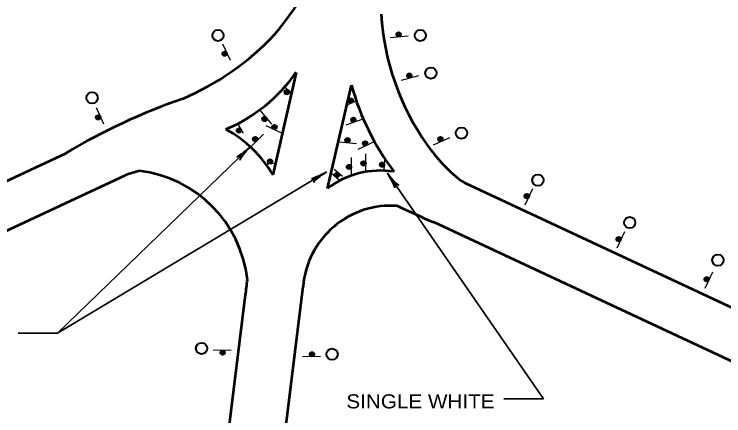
# Model space of a CAD drawing. Extents: x 393 to 1249, y -102 to 530.
# Drawn here: x 840.2 to 962.8, y 381.2 to 450.6 of the extents above; entities that cross this region are included whole.
import ezdxf
from ezdxf.enums import TextEntityAlignment as Align

# ---------------------------------------------------------------- set-up
doc = ezdxf.new("R2010")
doc.units = 0
doc.header["$LTSCALE"] = 0.97
doc.layers.add('1', color=7, linetype='Continuous', lineweight=40)
doc.layers.add('4', color=7, linetype='Continuous', lineweight=25)

msp = doc.modelspace()

# ---------------------------------------------------------------- linework, layer by layer
at = {"layer": '1', "lineweight": 53}
for p, q in [((884.8875, 422.8101), (888.97, 440.4933)), ((894.3206, 420.4602), (898.4419, 438.3114)), ((674.5966, 345.1922), (849.021, 426.5276)), ((677.8828, 338.1447), (859.4161, 422.795)), ((1080.9208, 345.4442), (918.2161, 421.3147)), ((1076.6773, 338.1447), (912.6644, 414.6252)), ((882.4301, 341.0291), (890.104, 403.5283)), ((872.7621, 342.0454), (880.1317, 402.0688))]:
    msp.add_line(p, q, dxfattribs=at)
at = {"layer": '1', "lineweight": 35}
for p, q in [((847.6419, 395.4762), (880.8897, 427.5989)), ((847.6419, 395.4762), (894.1049, 423.3294)), ((931.6085, 384.0908), (904.6769, 423.1261)), ((840.8379, 395.4762), (847.6419, 395.4762)), ((924.8045, 384.0908), (931.6085, 384.0908))]:
    msp.add_line(p, q, dxfattribs=at)
at = {"layer": '1'}
for centre, radius in [((875.3758, 446.9163), 0.972), ((910.3447, 446.9163), 0.972), ((906.5895, 447.0928), 0.3791), ((906.5807, 447.0822), 0.35), ((906.5798, 447.0919), 0.3305), ((906.6072, 447.1138), 0.3402), ((906.5895, 447.0928), 0.3013), ((906.5895, 447.0928), 0.2819), ((906.5798, 447.0919), 0.2722), ((906.5798, 447.0919), 0.2527), ((906.579, 447.1016), 0.2335), ((906.5781, 447.1113), 0.2138), ((906.5781, 447.1113), 0.1944), ((906.5554, 447.1483), 0.1555), ((906.5764, 447.1306), 0.175), ((906.5604, 447.0902), 0.1555), ((906.5642, 447.1588), 0.1461), ((906.5537, 447.1677), 0.1166), ((906.5528, 447.1774), 0.0977), ((906.5701, 447.0911), 0.1069), ((906.552, 447.187), 0.0778), ((906.5503, 447.2064), 0.0583), ((906.5486, 447.2258), 0.0389), ((906.5469, 447.2451), 0.0194), ((906.7217, 447.1433), 0.00972), ((876.5287, 443.7638), 0.3791), ((876.5028, 443.7732), 0.3402), ((876.5416, 443.7591), 0.35), ((876.5328, 443.755), 0.3305), ((876.5287, 443.7638), 0.3013), ((876.5287, 443.7638), 0.2819), ((876.5328, 443.755), 0.2722), ((876.5328, 443.755), 0.2527), ((876.524, 443.7509), 0.2335), ((876.5152, 443.7467), 0.2138), ((876.5152, 443.7467), 0.1944), ((876.4975, 443.7385), 0.175), ((876.4752, 443.7174), 0.1461), ((876.4881, 443.7127), 0.1555), ((876.4705, 443.7045), 0.1166), ((876.4617, 443.7004), 0.0977), ((876.4529, 443.6963), 0.0778), ((876.4353, 443.6881), 0.0583), ((876.4177, 443.6798), 0.0389), ((876.4, 443.6716), 0.0194), ((876.541, 443.7373), 0.1555), ((876.4359, 443.8707), 0.00972), ((876.5369, 443.7462), 0.1069), ((908.4289, 439.9822), 0.3791), ((908.422, 439.9702), 0.35), ((908.4195, 439.9796), 0.3305), ((908.4426, 440.006), 0.3402), ((912.1745, 440.4105), 0.972), ((908.4289, 439.9822), 0.3013), ((908.4289, 439.9822), 0.2819), ((908.4195, 439.9796), 0.2722), ((908.4195, 439.9796), 0.2527), ((908.417, 439.989), 0.2335), ((908.4145, 439.9984), 0.2138), ((908.4145, 439.9984), 0.1944), ((908.3856, 440.0309), 0.1555), ((908.4094, 440.0172), 0.175), ((908.4007, 439.9746), 0.1555), ((908.3925, 440.0428), 0.1461), ((908.3806, 440.0497), 0.1166), ((908.3781, 440.0591), 0.0977), ((908.3756, 440.0685), 0.0778), ((908.4101, 439.9771), 0.1069), ((908.3705, 440.0873), 0.0583), ((908.3655, 440.106), 0.0389), ((908.3605, 440.1248), 0.0194), ((908.5503, 440.0549), 0.00972), ((853.6218, 436.141), 0.972), ((887.2679, 437.1153), 0.3791), ((887.2601, 437.1313), 0.3402), ((887.3012, 437.1349), 0.35), ((887.2949, 437.1275), 0.3305), ((887.2875, 437.1337), 0.3013), ((887.2875, 437.1337), 0.2819), ((887.2949, 437.1275), 0.2722), ((887.2949, 437.1275), 0.2527), ((887.2887, 437.12), 0.2335), ((887.2825, 437.1126), 0.2138), ((887.2825, 437.1126), 0.1944), ((887.27, 437.0977), 0.175), ((887.2587, 437.0691), 0.1461), ((887.2724, 437.0703), 0.1555), ((887.2599, 437.0554), 0.1166), ((887.3098, 437.115), 0.1555), ((887.2536, 437.048), 0.0977), ((887.2474, 437.0405), 0.0778), ((887.2349, 437.0256), 0.0583), ((887.2329, 437.0333), 0.0389), ((887.3024, 437.1212), 0.1069), ((887.2294, 437.0142), 0.0194), ((887.2498, 437.0223), 0.00972), ((898.3356, 435.6502), 0.3791), ((898.3393, 435.6117), 0.35), ((898.3352, 435.6205), 0.3305), ((898.3534, 435.6505), 0.3402), ((898.344, 435.6247), 0.3013), ((898.344, 435.6247), 0.2819), ((898.3352, 435.6205), 0.2722), ((898.3352, 435.6205), 0.2527), ((898.3311, 435.6294), 0.2335), ((898.327, 435.6382), 0.2138), ((898.327, 435.6382), 0.1944), ((898.2929, 435.6652), 0.1555), ((898.3187, 435.6558), 0.175), ((898.2976, 435.6781), 0.1461), ((898.3176, 435.6123), 0.1555), ((898.2847, 435.6828), 0.1166), ((898.2806, 435.6916), 0.0977), ((898.2765, 435.7004), 0.0778), ((898.2683, 435.718), 0.0583), ((898.3264, 435.6164), 0.1069), ((898.276, 435.7166), 0.0389), ((898.2602, 435.7278), 0.0194), ((898.2589, 435.706), 0.00972), ((854.6686, 432.7594), 0.3791), ((854.6428, 432.7688), 0.3402), ((854.6815, 432.7547), 0.35), ((854.6727, 432.7506), 0.3305), ((854.6686, 432.7594), 0.3013), ((854.6686, 432.7594), 0.2819), ((854.6727, 432.7506), 0.2722), ((854.6727, 432.7506), 0.2527), ((854.6639, 432.7465), 0.2335), ((854.6551, 432.7424), 0.2138), ((854.6551, 432.7424), 0.1944), ((854.6375, 432.7342), 0.175), ((854.6152, 432.7131), 0.1461), ((854.6281, 432.7084), 0.1555), ((854.6105, 432.7001), 0.1166), ((854.6017, 432.696), 0.0977), ((854.5929, 432.6919), 0.0778), ((854.5752, 432.6837), 0.0583), ((854.5576, 432.6755), 0.0389), ((854.54, 432.6673), 0.0194), ((854.681, 432.733), 0.1555), ((854.5759, 432.8663), 0.00972), ((854.6768, 432.7418), 0.1069), ((883.4068, 432.4789), 0.3791), ((883.3794, 432.4813), 0.3402), ((883.4205, 432.4777), 0.35), ((883.413, 432.4714), 0.3305), ((883.4068, 432.4789), 0.3013), ((883.4068, 432.4789), 0.2819), ((883.413, 432.4714), 0.2722), ((883.413, 432.4714), 0.2527), ((883.4056, 432.4652), 0.2335), ((883.3981, 432.4589), 0.2138), ((883.3981, 432.4589), 0.1944), ((883.3832, 432.4464), 0.175), ((883.3671, 432.4202), 0.1461), ((883.3808, 432.419), 0.1555), ((883.3659, 432.4065), 0.1166), ((883.3585, 432.4003), 0.0977), ((883.4255, 432.4565), 0.1555), ((883.351, 432.3941), 0.0778), ((883.3362, 432.3816), 0.0583), ((883.2895, 432.5581), 0.00972), ((883.3213, 432.3691), 0.0389), ((883.3064, 432.3566), 0.0194), ((883.4193, 432.464), 0.1069), ((898.7845, 432.3435), 0.3791), ((898.7787, 432.331), 0.35), ((898.7753, 432.3402), 0.3305), ((898.7961, 432.3684), 0.3402), ((898.7845, 432.3435), 0.3013), ((898.7845, 432.3435), 0.2819), ((898.7753, 432.3402), 0.2722), ((898.7753, 432.3402), 0.2527), ((898.772, 432.3493), 0.2335), ((898.7687, 432.3584), 0.2138), ((898.7687, 432.3584), 0.1944), ((898.7371, 432.3883), 0.1555), ((898.762, 432.3767), 0.175), ((898.7429, 432.4008), 0.1461), ((898.7571, 432.3335), 0.1555), ((898.7305, 432.4066), 0.1166), ((898.7271, 432.4157), 0.0977), ((898.7238, 432.4249), 0.0778), ((898.7172, 432.4431), 0.0583), ((898.7662, 432.3369), 0.1069), ((898.7105, 432.4614), 0.0389), ((898.7039, 432.4797), 0.0194), ((898.899, 432.4266), 0.00972), ((879.0003, 430.4948), 0.3791), ((878.9985, 430.5126), 0.3402), ((879.0383, 430.5019), 0.35), ((879.0299, 430.497), 0.3305), ((879.025, 430.5054), 0.3013), ((879.025, 430.5054), 0.2819), ((879.0299, 430.497), 0.2722), ((879.0299, 430.497), 0.2527), ((879.0215, 430.4922), 0.2335), ((879.013, 430.4873), 0.2138), ((879.013, 430.4873), 0.1944), ((878.9962, 430.4776), 0.175), ((878.9758, 430.4546), 0.1461), ((878.9891, 430.451), 0.1555), ((878.9723, 430.4413), 0.1166), ((878.9638, 430.4365), 0.0977), ((878.9554, 430.4316), 0.0778), ((879.0396, 430.4802), 0.1555), ((879.0347, 430.4886), 0.1069), ((885.1453, 431.0803), 0.3791), ((885.1324, 431.0756), 0.35), ((885.1365, 431.0844), 0.3305), ((885.1711, 431.0897), 0.3402), ((885.1453, 431.0803), 0.3013), ((885.1453, 431.0803), 0.2819), ((885.1365, 431.0844), 0.2722), ((885.1365, 431.0844), 0.2527), ((885.1406, 431.0932), 0.2335), ((885.1447, 431.102), 0.2138), ((885.1447, 431.102), 0.1944), ((885.1189, 431.0926), 0.1555), ((885.1529, 431.1196), 0.175), ((885.1435, 431.1455), 0.1555), ((885.1564, 431.1502), 0.1461), ((885.1277, 431.0885), 0.1069), ((885.1517, 431.1631), 0.1166), ((885.1558, 431.1719), 0.0977), ((885.1599, 431.1807), 0.0778), ((885.1682, 431.1983), 0.0583), ((885.1764, 431.216), 0.0389), ((885.1846, 431.2336), 0.0194), ((885.2851, 431.058), 0.00972), ((917.4604, 430.0417), 0.972), ((878.9386, 430.4219), 0.0583), ((878.9393, 430.4297), 0.0389), ((878.9295, 430.413), 0.0194), ((878.9514, 430.4136), 0.00972), ((881.7927, 429.0166), 0.3791), ((881.7927, 429.0028), 0.35), ((881.7927, 429.0441), 0.3402), ((881.7858, 429.0097), 0.3305), ((881.7927, 429.0166), 0.3013), ((881.7927, 429.0166), 0.2819), ((881.7858, 429.0097), 0.2722), ((881.7858, 429.0097), 0.2527), ((913.8263, 428.9956), 0.3791), ((913.8216, 428.9827), 0.35), ((913.8175, 428.9915), 0.3305), ((913.8357, 429.0215), 0.3402), ((913.8263, 428.9956), 0.3013), ((913.8263, 428.9956), 0.2819), ((913.8175, 428.9915), 0.2722), ((881.779, 429.0166), 0.2335), ((881.7721, 429.0234), 0.2138), ((881.7309, 429.0372), 0.1555), ((881.7721, 429.0234), 0.1944), ((881.7584, 429.0372), 0.175), ((881.7309, 429.0509), 0.1461), ((881.7171, 429.0509), 0.1166), ((881.7102, 429.0578), 0.0977), ((881.7721, 428.9959), 0.1555), ((881.7034, 429.0647), 0.0778), ((881.6896, 429.0784), 0.0583), ((881.6759, 429.0922), 0.0389), ((881.6621, 429.1059), 0.0194), ((881.779, 429.0028), 0.1069), ((881.8614, 429.1403), 0.00972), ((897.7591, 428.8098), 0.3791), ((897.7486, 428.8009), 0.35), ((897.7494, 428.8106), 0.3305), ((897.7802, 428.8274), 0.3402), ((897.7591, 428.8098), 0.3013), ((897.7591, 428.8098), 0.2819), ((897.7494, 428.8106), 0.2722), ((897.7494, 428.8106), 0.2527), ((897.7503, 428.8203), 0.2335), ((897.7511, 428.83), 0.2138), ((897.7511, 428.83), 0.1944), ((897.7301, 428.8123), 0.1555), ((897.7528, 428.8493), 0.175), ((897.7351, 428.8704), 0.1555), ((897.7457, 428.8792), 0.1461), ((897.7368, 428.8898), 0.1166), ((897.7397, 428.8115), 0.1069), ((897.7377, 428.8995), 0.0977), ((897.7385, 428.9091), 0.0778), ((897.7402, 428.9285), 0.0583), ((897.7419, 428.9479), 0.0389), ((897.7436, 428.9672), 0.0194), ((897.8981, 428.8366), 0.00972), ((900.8064, 428.2625), 0.3791), ((900.8017, 428.2496), 0.35), ((900.7976, 428.2584), 0.3305), ((900.8158, 428.2883), 0.3402), ((900.8064, 428.2625), 0.3013), ((900.8064, 428.2625), 0.2819), ((900.7976, 428.2584), 0.2722), ((900.7976, 428.2584), 0.2527), ((900.7935, 428.2672), 0.2335), ((900.7894, 428.276), 0.2138), ((900.7894, 428.276), 0.1944), ((900.7554, 428.303), 0.1555), ((900.7812, 428.2936), 0.175), ((900.7601, 428.3159), 0.1461), ((900.78, 428.2502), 0.1555), ((900.7471, 428.3206), 0.1166), ((900.743, 428.3295), 0.0977), ((900.7389, 428.3383), 0.0778), ((900.7307, 428.3559), 0.0583), ((900.7888, 428.2543), 0.1069), ((900.7225, 428.3735), 0.0389), ((900.7143, 428.3911), 0.0194), ((900.9133, 428.3552), 0.00972), ((913.8175, 428.9915), 0.2527), ((913.8134, 429.0003), 0.2335), ((913.8093, 429.0091), 0.2138), ((913.8093, 429.0091), 0.1944), ((913.7752, 429.0362), 0.1555), ((913.801, 429.0268), 0.175), ((913.7799, 429.0491), 0.1461), ((913.7999, 428.9833), 0.1555), ((913.767, 429.0538), 0.1166), ((913.7629, 429.0626), 0.0977), ((913.7588, 429.0714), 0.0778), ((913.7506, 429.089), 0.0583), ((913.8087, 428.9874), 0.1069), ((913.7424, 429.1066), 0.0389), ((913.7341, 429.1243), 0.0194), ((913.9332, 429.0884), 0.00972), ((884.3789, 425.1521), 0.3791), ((884.3692, 425.1147), 0.35), ((884.3684, 425.1244), 0.3305), ((884.3957, 425.1463), 0.3402), ((884.378, 425.1252), 0.3013), ((884.378, 425.1252), 0.2819), ((884.3684, 425.1244), 0.2722), ((884.3684, 425.1244), 0.2527), ((884.3675, 425.1341), 0.2335), ((884.3667, 425.1438), 0.2138), ((884.3667, 425.1438), 0.1944), ((884.3439, 425.1808), 0.1555), ((884.365, 425.1631), 0.175), ((884.349, 425.1227), 0.1555), ((884.3527, 425.1913), 0.1461), ((884.3422, 425.2002), 0.1166), ((884.3414, 425.2098), 0.0977), ((884.3587, 425.1235), 0.1069), ((884.3405, 425.2195), 0.0778), ((884.3388, 425.2389), 0.0583), ((884.3456, 425.2349), 0.0389), ((884.3346, 425.2508), 0.0194), ((884.3259, 425.2307), 0.00972), ((898.0182, 424.2025), 0.3791), ((897.9987, 424.222), 0.3402), ((898.0279, 424.1928), 0.35), ((898.0182, 424.1928), 0.3305), ((898.0182, 424.2025), 0.3013), ((898.0182, 424.2025), 0.2819), ((898.0182, 424.1928), 0.2722), ((898.0182, 424.1928), 0.2527), ((898.0084, 424.1928), 0.2335), ((897.9987, 424.1928), 0.2138), ((897.9987, 424.1928), 0.1944), ((897.9793, 424.1928), 0.175), ((900.524, 424.8145), 0.3791), ((900.5045, 424.8339), 0.3402), ((900.5337, 424.8048), 0.35), ((900.524, 424.8048), 0.3305), ((900.524, 424.8145), 0.3013), ((900.524, 424.8145), 0.2819), ((900.524, 424.8048), 0.2722), ((900.524, 424.8048), 0.2527), ((900.5142, 424.8048), 0.2335), ((900.5045, 424.8048), 0.2138), ((900.4559, 424.795), 0.1461), ((900.5045, 424.8048), 0.1944), ((900.4851, 424.8048), 0.175), ((900.4656, 424.7853), 0.1555), ((900.4462, 424.7853), 0.1166), ((900.4365, 424.7853), 0.0977), ((900.4268, 424.7853), 0.0778), ((900.4073, 424.7853), 0.0583), ((900.3879, 424.7853), 0.0389), ((900.3684, 424.7853), 0.0194), ((900.524, 424.7853), 0.1555), ((900.524, 424.795), 0.1069), ((900.4851, 424.9506), 0.00972), ((903.7317, 424.5864), 0.3791), ((903.7403, 424.602), 0.3402), ((903.7668, 424.5704), 0.35), ((903.7572, 424.5712), 0.3305), ((903.758, 424.5809), 0.3013), ((903.758, 424.5809), 0.2819), ((903.7572, 424.5712), 0.2722), ((903.7572, 424.5712), 0.2527), ((903.7475, 424.5721), 0.2335), ((903.7378, 424.5729), 0.2138), ((903.6974, 424.5569), 0.1555), ((903.6885, 424.5675), 0.1461), ((903.7378, 424.5729), 0.1944), ((903.7184, 424.5746), 0.175), ((903.678, 424.5586), 0.1166), ((903.6683, 424.5595), 0.0977), ((903.6586, 424.5603), 0.0778), ((903.6393, 424.562), 0.0583), ((903.7555, 424.5519), 0.1555), ((903.6444, 424.568), 0.0389), ((903.6268, 424.5599), 0.0194), ((903.6451, 424.5479), 0.00972), ((903.7563, 424.5615), 0.1069), ((895.9284, 422.8267), 0.3791), ((895.901, 422.8243), 0.3402), ((895.9421, 422.8279), 0.35), ((895.9358, 422.8204), 0.3305), ((897.9501, 424.1831), 0.1461), ((897.9598, 424.1734), 0.1555), ((897.9404, 424.1734), 0.1166), ((897.9307, 424.1734), 0.0977), ((897.921, 424.1734), 0.0778), ((897.9015, 424.1734), 0.0583), ((897.8821, 424.1734), 0.0389), ((897.8626, 424.1734), 0.0194), ((898.0182, 424.1734), 0.1555), ((898.0182, 424.1831), 0.1069), ((897.9793, 424.3386), 0.00972), ((895.9284, 422.8267), 0.3013), ((895.9284, 422.8267), 0.2819), ((895.9358, 422.8204), 0.2722), ((895.9358, 422.8204), 0.2527), ((895.9296, 422.813), 0.2335), ((895.9233, 422.8056), 0.2138), ((895.9233, 422.8056), 0.1944), ((895.9108, 422.7907), 0.175), ((895.8995, 422.7621), 0.1461), ((895.9132, 422.7633), 0.1555), ((895.9007, 422.7484), 0.1166), ((895.7991, 422.8844), 0.00972), ((895.9507, 422.8079), 0.1555), ((895.8945, 422.7409), 0.0977), ((895.8882, 422.7335), 0.0778), ((895.8757, 422.7186), 0.0583), ((895.8632, 422.7037), 0.0389), ((895.9433, 422.8142), 0.1069), ((895.8698, 422.7056), 0.0194), ((930.6754, 421.9094), 0.972), ((928.7513, 419.1461), 0.3791), ((928.7419, 419.1719), 0.3402), ((928.756, 419.1331), 0.35), ((928.7472, 419.1372), 0.3305), ((928.7513, 419.1461), 0.3013), ((928.7513, 419.1461), 0.2819), ((928.7472, 419.1372), 0.2722), ((928.7472, 419.1372), 0.2527), ((928.7383, 419.1414), 0.2335), ((928.7295, 419.1455), 0.2138), ((928.6861, 419.1443), 0.1555), ((928.7295, 419.1455), 0.1944), ((928.6814, 419.1572), 0.1461), ((928.7119, 419.1537), 0.175), ((928.6685, 419.1525), 0.1166), ((928.6597, 419.1566), 0.0977), ((928.6508, 419.1607), 0.0778), ((928.6332, 419.1689), 0.0583), ((928.6156, 419.1771), 0.0389), ((928.598, 419.1853), 0.0194), ((928.7389, 419.1196), 0.1555), ((928.743, 419.1284), 0.1069), ((928.7735, 419.2858), 0.00972), ((946.5335, 414.5903), 0.972), ((944.6284, 411.7142), 0.3791), ((944.619, 411.7401), 0.3402), ((944.6331, 411.7013), 0.35), ((944.6243, 411.7054), 0.3305), ((944.6284, 411.7142), 0.3013), ((944.6284, 411.7142), 0.2819), ((944.6243, 411.7054), 0.2722), ((944.6243, 411.7054), 0.2527), ((944.6155, 411.7095), 0.2335), ((944.6067, 411.7136), 0.2138), ((944.5632, 411.7124), 0.1555), ((944.6067, 411.7136), 0.1944), ((944.5585, 411.7254), 0.1461), ((944.5891, 411.7218), 0.175), ((944.5456, 411.7207), 0.1166), ((944.5368, 411.7248), 0.0977), ((944.528, 411.7289), 0.0778), ((944.5104, 411.7371), 0.0583), ((944.4927, 411.7453), 0.0389), ((944.4751, 411.7535), 0.0194), ((944.6161, 411.6878), 0.1555), ((944.6202, 411.6966), 0.1069), ((944.6507, 411.854), 0.00972), ((961.7815, 408.0845), 0.972), ((959.8298, 404.7891), 0.3791), ((959.8204, 404.815), 0.3402), ((959.8345, 404.7762), 0.35), ((959.8257, 404.7803), 0.3305), ((959.8298, 404.7891), 0.3013), ((959.8298, 404.7891), 0.2819), ((959.8257, 404.7803), 0.2722), ((959.8257, 404.7803), 0.2527), ((959.8169, 404.7844), 0.2335), ((959.8081, 404.7885), 0.2138), ((959.7646, 404.7873), 0.1555), ((959.8081, 404.7885), 0.1944), ((959.7599, 404.8003), 0.1461), ((959.7905, 404.7967), 0.175), ((959.747, 404.7956), 0.1166), ((959.7382, 404.7997), 0.0977), ((959.7294, 404.8038), 0.0778), ((959.7118, 404.812), 0.0583), ((959.6942, 404.8202), 0.0389), ((959.6766, 404.8284), 0.0194), ((959.8175, 404.7627), 0.1555), ((959.8216, 404.7715), 0.1069), ((959.8521, 404.9289), 0.00972), ((872.5294, 392.8364), 0.972), ((876.1684, 392.1121), 0.3791), ((876.1783, 392.1216), 0.35), ((895.0966, 391.8199), 0.972), ((876.1486, 392.093), 0.3402), ((876.1781, 392.1119), 0.3305), ((876.1684, 392.1121), 0.3013), ((876.1684, 392.1121), 0.2819), ((876.1781, 392.1119), 0.2722), ((876.1781, 392.1119), 0.2527), ((876.1779, 392.1022), 0.2335), ((876.1778, 392.0925), 0.2138), ((876.1778, 392.0925), 0.1944), ((876.1774, 392.073), 0.175), ((876.0317, 392.0756), 0.00972), ((876.1866, 392.0437), 0.1461), ((876.1965, 392.0533), 0.1555), ((876.1976, 392.1116), 0.1555), ((876.1962, 392.0338), 0.1166), ((876.1878, 392.1117), 0.1069), ((876.196, 392.0241), 0.0977), ((876.1959, 392.0144), 0.0778), ((876.1955, 391.9949), 0.0583), ((876.1952, 391.9755), 0.0389), ((876.1948, 391.9561), 0.0194), ((891.6199, 391.8278), 0.3791), ((891.6001, 391.8469), 0.3402), ((891.6298, 391.8182), 0.35), ((891.6296, 391.8279), 0.3305), ((891.6199, 391.8278), 0.3013), ((891.6199, 391.8278), 0.2819), ((891.6296, 391.8279), 0.2722), ((891.6296, 391.8279), 0.2527), ((891.6294, 391.8377), 0.2335), ((891.6293, 391.8474), 0.2138), ((891.6293, 391.8474), 0.1944), ((891.6289, 391.8668), 0.175), ((891.4831, 391.8643), 0.00972), ((891.6381, 391.8961), 0.1461), ((891.648, 391.8866), 0.1555), ((891.649, 391.8283), 0.1555), ((891.6477, 391.906), 0.1166), ((891.6393, 391.8281), 0.1069), ((891.6475, 391.9157), 0.0977), ((891.6473, 391.9255), 0.0778), ((891.647, 391.9449), 0.0583), ((891.6467, 391.9643), 0.0389), ((891.6463, 391.9838), 0.0194)]:
    msp.add_circle(centre, radius, dxfattribs=at)
at = {"layer": '1', "lineweight": 53}
for centre, radius, start, end in [((838.0728, 486.6848), 61.5345, 319.99373, 340.00633), ((850.4999, 479.7458), 47.6298, 293.22493, 316.77535), ((865.562, 456.9458), 28.5302, 293.08907, 324.91903), ((903.6451, 335.8354), 105.872, 108.93946, 121.06067), ((866.5185, 412.0069), 21.3097, 30.45813, 61.29534), ((938.0157, 446.9321), 32.5487, 215.37581, 230.30556), ((877.337, 368.3284), 57.3391, 105.73397, 108.21258), ((859.2772, 402.3578), 21.3097, 6.34554, 83.3181), ((903.4999, 408.4109), 15.1552, 81.2821, 127.28757), ((904.9128, 399.4693), 25.5773, 58.65985, 61.21963), ((905.2126, 402.3401), 15.1552, 85.47195, 175.50333), ((999.7154, 616.1069), 219.4829, 244.83939, 246.63305), ((825.3366, 410.1386), 55.3862, 351.62224, 354.37838), ((859.2772, 402.3578), 21.3097, 6.32047, 6.34554)]:
    msp.add_arc(centre, radius, start, end, dxfattribs=at)
for centre, major_axis, start_param, end_param in [((942.696, 453.3676), (1.5595, -41.973), 4.74374174, 5.32357861), ((936.1557, 449.2676), (-7.3859, 41.3475), 1.66994276, 2.07069625)]:
    msp.add_ellipse(centre, major_axis=major_axis, ratio=0.934252, start_param=start_param, end_param=end_param, dxfattribs=at)
at = {"layer": '1'}
for centre, major_axis, ratio, start_param, end_param in [((879.9636, 426.99), (1.3464, 1.0635), 0.07063, 3.14071475, 5.41810995), ((880.3136, 426.6687), (1.1428, 1.3152), 0.122415, 0.89635335, 3.14159265), ((893.0649, 422.9458), (-1.5521, -0.7314), 0.07063, 6.28230741, 8.55970261), ((893.3332, 422.5537), (1.4107, 1.0226), 0.122415, 0.89635335, 3.14159265), ((905.1261, 422.1129), (-0.829, 1.5022), 0.07063, 3.14071475, 5.41810995), ((905.5002, 422.4056), (-1.1106, 1.3425), 0.122415, 0.89635335, 3.14159265)]:
    msp.add_ellipse(centre, major_axis=major_axis, ratio=ratio, start_param=start_param, end_param=end_param, dxfattribs=at)
at = {"layer": '4'}
for p, q in [((905.1436, 446.5565), (908.2423, 446.8276)), ((877.5271, 442.5885), (876.2127, 445.4074)), ((907.0981, 439.2029), (910.1026, 440.0079)), ((888.1813, 436.886), (886.8432, 438.009)), ((897.7418, 434.9191), (899.3251, 435.6575)), ((855.6671, 431.5842), (854.3526, 434.4031)), ((884.6754, 431.6022), (882.6761, 433.9847)), ((897.5267, 431.4512), (900.4496, 432.515)), ((900.6645, 431.8324), (900.6699, 431.8349)), ((879.7802, 429.9669), (878.9068, 431.4798)), ((883.625, 431.3387), (886.4439, 430.0243)), ((881.0299, 427.6763), (883.2293, 429.8756)), ((912.651, 427.9971), (915.4702, 429.3116)), ((896.2422, 428.5326), (899.3407, 428.2615)), ((899.6311, 427.264), (902.4502, 428.5784)), ((902.0192, 428.9058), (902.0741, 428.9258)), ((898.4265, 422.7153), (898.4264, 425.8259)), ((900.9323, 423.3272), (900.9324, 426.4376)), ((883.5708, 424.6684), (885.3112, 424.8206)), ((904.0679, 423.7067), (904.2202, 425.447)), ((896.8706, 422.5689), (895.48, 423.7356)), ((896.3334, 421.9284), (894.9428, 423.0954)), ((928.4928, 417.6257), (929.8073, 420.4448)), ((944.37, 410.1939), (945.6845, 413.0129)), ((959.5714, 403.2688), (960.886, 406.0879)), ((877.6625, 392.4944), (874.5523, 392.5485)), ((893.114, 391.4455), (890.0038, 391.3913))]:
    msp.add_line(p, q, dxfattribs=at)
for centre in [(906.5992, 447.0936), (876.5246, 443.7726), (908.4383, 439.9847), (887.2731, 437.1205), (898.3381, 435.6433), (854.6645, 432.7682), (883.4005, 432.4863), (898.7936, 432.3468), (879.007, 430.498), (885.1541, 431.0762), (881.7996, 429.0234), (913.8351, 428.9997), (897.7688, 428.8089), (900.8152, 428.2666), (884.3789, 425.1447), (898.0182, 424.2122), (900.524, 424.8242), (903.7389, 424.5851), (895.9209, 422.8329), (928.7554, 419.1549), (944.6325, 411.723), (959.8339, 404.7979), (876.1587, 392.1122), (891.6102, 391.8276)]:
    msp.add_circle(centre, 0.3985, dxfattribs=at)

# ---------------------------------------------------------------- texts
at = {"layer": '1', "width": 1.1}
msp.add_text('SINGLE WHITE', height=2.43, dxfattribs=at).set_placement((910.3694, 382.4692), align=Align.CENTER)

doc.saveas('drawing.dxf')
